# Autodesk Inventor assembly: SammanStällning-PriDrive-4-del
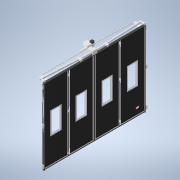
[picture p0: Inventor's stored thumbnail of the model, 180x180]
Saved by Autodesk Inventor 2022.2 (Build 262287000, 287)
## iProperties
Created: 2022-02
Part Number: SammanStällning-PriDrive-4-del
Document SubType Name: Assembly
Designer: cl
Author: cl
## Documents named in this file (23)
- G:\AutoCad\Carl Lund\3D-modeller systemlösningar\3D-modell-systemlösning-2022\SammanStällning-PriDrive-4-del.iam
- G:\AutoCad\Carl Lund\3D-modeller systemlösningar\3D-modell-systemlösning-2022\Parts\BladKomplett2022.iam
- G:\AutoCad\Carl Lund\3D-modeller systemlösningar\3D-modell-systemlösning-2022\Parts\MellanGångjärnH.ipt
- G:\AutoCad\Carl Lund\3D-modeller systemlösningar\3D-modell-systemlösning-2022\Parts\MellanGångjärnV.ipt
- G:\AutoCad\Carl Lund\3D-modeller systemlösningar\3D-modell-systemlösning-2022\Parts\Karmstyrning.ipt
- G:\AutoCad\Carl Lund\3D-modeller systemlösningar\3D-modell-systemlösning-2022\Parts\SidotätningUppe.ipt
- G:\AutoCad\Carl Lund\3D-modeller systemlösningar\3D-modell-systemlösning-2022\Parts\SidoTätning.ipt
- G:\AutoCad\Carl Lund\3D-modeller systemlösningar\3D-modell-systemlösning-2022\Parts\SläpList.ipt
- G:\AutoCad\Carl Lund\3D-modeller systemlösningar\3D-modell-systemlösning-2022\Parts\GummilistMellan.ipt
- G:\AutoCad\Carl Lund\3D-modeller systemlösningar\3D-modell-systemlösning-2022\Styrande.iam
- G:\AutoCad\Carl Lund\3D-modeller systemlösningar\3D-modell-systemlösning-2022\Parts\PriDrive\Karmgångjärn-PriDrive.ipt
- G:\AutoCad\Carl Lund\3D-modeller systemlösningar\3D-modell-systemlösning-2022\Parts\PriDrive\VinkeljärnStyrskena2.ipt
- G:\AutoCad\Carl Lund\3D-modeller systemlösningar\3D-modell-systemlösning-2022\Parts\PriDrive\VinkeljärnStyrskena.ipt
- G:\AutoCad\Carl Lund\3D-modeller systemlösningar\3D-modell-systemlösning-2022\Parts\StyrrulleH.ipt
- G:\AutoCad\Carl Lund\3D-modeller systemlösningar\3D-modell-systemlösning-2022\Parts\StyrrulleV.ipt
- G:\AutoCad\Carl Lund\3D-modeller systemlösningar\3D-modell-systemlösning-2022\Parts\MotorPlatta.ipt
- G:\AutoCad\Carl Lund\3D-modeller systemlösningar\3D-modell-systemlösning-2022\Parts\Länkarm-4Del.ipt
- G:\AutoCad\Carl Lund\3D-modeller systemlösningar\3D-modell-systemlösning-2022\Parts\Länkarm2-4Del.ipt
- G:\AutoCad\Carl Lund\3D-modeller systemlösningar\3D-modell-systemlösning-2022\Parts\MotorKåpa.ipt
- G:\AutoCad\Carl Lund\3D-modeller systemlösningar\3D-modell-systemlösning-2022\Parts\Motor.ipt
- G:\AutoCad\Carl Lund\3D-modeller systemlösningar\3D-modell-systemlösning-2022\Parts\Växellåda.ipt
- G:\AutoCad\Carl Lund\3D-modeller systemlösningar\3D-modell-systemlösning-2022\Parts\Styrskena-PD.ipt
- G:\AutoCad\Carl Lund\3D-modeller systemlösningar\3D-modell-systemlösning-2022\Parts\Logga.ipt
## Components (47 placed, 21 different names)
1. Logga:1 — Mate:196, Mate:197, Mate:198
2. BladKomplett2022:1 [sub-assembly] — Mate:1, Mate:2, Flush:1, Flush:2, Flush:3, Flush:8, Flush:28, Flush:29, Mate:28, Flush:30, Mate:42, Mate:39, Mate:43, Flush:99, Flush:100, Flush:101, Flush:102, Flush:103, Flush:104, Flush:112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
3. BladKomplett2022:2 [sub-assembly] — Flush:2, Flush:3, Flush:8, Flush:106, Mate:52, Flush:107, Flush:118, Flush:121, Mate:65, Flush:148, Flush:149, Mate:185, Flush:182, Flush:183, Flush:188, Mate:189
4. BladKomplett2022:3 [sub-assembly] — Flush:30, Flush:101, Flush:102, Mate:53, Flush:114, Flush:115, Flush:180
5. BladKomplett2022:4 [sub-assembly] — Flush:32, Flush:100, Flush:103, Mate:54, Flush:122, Flush:123, Flush:128, Mate:64, Flush:146, Flush:147, Flush:178
6. BladKomplett2022:5 [sub-assembly] — Flush:31, Flush:99, Flush:104, Flush:129, Mate:55, Flush:130, Mate:63, Flush:144, Flush:145, Mate:186, Flush:184, Flush:185, Flush:186, Flush:189
7. BladKomplett2022:6 [sub-assembly] — Mate:28, Flush:28, Flush:29, Flush:31, Flush:32, Mate:38, Flush:131, Flush:134, Flush:137, Mate:56, Flush:138, Flush:139, Mate:58, Mate:59, Mate:62, Flush:142, Flush:143, Flush:152, Mate:69, Mate:70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
8. Karmstyrning:2 — Mate:38, Mate:56, Flush:138, Flush:141
9. Karmstyrning:3 — Mate:39, Mate:43, Flush:140
10. Karmstyrning:4 — Mate:42, Mate:60, Mate:61, Flush:141
11. Karmstyrning:1 — Flush:139, Mate:58, Mate:59, Flush:140
12. MellanGångjärnV:3 — Flush:110, Flush:111, Flush:113
13. MellanGångjärnV:2 — Flush:108, Flush:109, Flush:110, Flush:111, Flush:112
14. MellanGångjärnV:1 — Flush:106, Mate:52, Flush:107, Flush:108, Flush:109
15. MellanGångjärnH:2 — Flush:116, Flush:117, Flush:118, Flush:119, Flush:120
16. MellanGångjärnH:3 — Flush:119, Flush:120, Flush:121
17. MellanGångjärnH:1 — Mate:53, Flush:114, Flush:115, Flush:116, Flush:117
18. MellanGångjärnV:6 — Flush:124, Flush:125, Flush:126, Flush:127, Flush:128
19. MellanGångjärnV:5 — Flush:126, Flush:127, Flush:129
20. MellanGångjärnV:4 — Mate:54, Flush:122, Flush:123, Flush:124, Flush:125
21. MellanGångjärnH:5 — Flush:132, Flush:133, Flush:134
22. MellanGångjärnH:6 — Flush:135, Flush:136, Flush:137
23. MellanGångjärnH:4 — Mate:55, Flush:130, Flush:131, Flush:132, Flush:133, Flush:135, Flush:136
24. GummilistMellan:2 — Mate:63, Flush:144, Flush:145
25. GummilistMellan:3 — Mate:64, Flush:146, Flush:147
26. GummilistMellan:4 — Mate:65, Flush:148, Flush:149
27. GummilistMellan:5 — Mate:66, Flush:150, Flush:151
28. SidotätningUppe:1 — Mate:67, Mate:68, Flush:152, Mate:71, Mate:74
29. SidoTätning:1 — Mate:69, Mate:70, Mate:71, Mate:76
30. SidoTätning:2 — Mate:72, Mate:73, Mate:74
31. SläpList:1 — Mate:75, Flush:153, Mate:76
32. GummilistMellan:1 — Mate:62, Flush:142, Flush:143
33. Karmgångjärn-PriDrive:1 — Mate:177, Flush:176, Mate:178, Flush:177, Flush:179, Mate:188, Tangent:3, Tangent:4
34. VinkeljärnStyrskena2:1 — Flush:179, Flush:180, Mate:181, Mate:183, Flush:187
35. VinkeljärnStyrskena2:2 — Flush:177, Flush:178, Mate:180, Flush:181, Mate:184
36. VinkeljärnStyrskena:1 — Mate:182, Flush:181, Flush:186
37. VinkeljärnStyrskena:2 — Mate:187, Flush:187, Flush:188
38. StyrrulleH:1 — Mate:185, Flush:182, Flush:183, Tangent:2
39. StyrrulleV:1 — Mate:186, Flush:184, Flush:185, Tangent:1
40. Styrskena-PD:2 — Flush:174, Mate:181, Mate:183, Tangent:2, Mate:187
41. Styrskena-PD:1 — Flush:174, Mate:179, Mate:180, Mate:182, Mate:184, Tangent:1
42. Länkarm-4Del:1 — Flush:190, Mate:190, Tangent:3, Flush:191
43. Länkarm2-4Del:1 — Mate:191, Flush:191, Tangent:4
44. MotorKåpa:1 — Mate:195, Flush:195, Flush:196
45. Motor:1 — Mate:193, Flush:194, Mate:194, Mate:195, Flush:195, Flush:196
46. Växellåda:1 — Mate:192, Flush:192, Flush:193, Flush:194, Mate:194
47. MotorPlatta:1 — Mate:188, Flush:189, Mate:189, Flush:190, Mate:190, Mate:191, Mate:192, Flush:192, Flush:193, Mate:193
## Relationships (142: Flush 85, Mate 53, Tangent 4)
- Mate:1: BladKomplett2022:1
- Mate:2: BladKomplett2022:1
- Flush:1: BladKomplett2022:1
- Flush:2: BladKomplett2022:1 ↔ BladKomplett2022:2
- Flush:3: BladKomplett2022:1 ↔ BladKomplett2022:2
- Flush:8: BladKomplett2022:1 ↔ BladKomplett2022:2
- Mate:28: BladKomplett2022:1 ↔ BladKomplett2022:6
- Flush:28: BladKomplett2022:1 ↔ BladKomplett2022:6
- Flush:29: BladKomplett2022:1 ↔ BladKomplett2022:6
- Flush:30: BladKomplett2022:1 ↔ BladKomplett2022:3
- Flush:31: BladKomplett2022:5 ↔ BladKomplett2022:6
- Flush:32: BladKomplett2022:4 ↔ BladKomplett2022:6
- Mate:38: BladKomplett2022:6 ↔ Karmstyrning:2
- Mate:39: BladKomplett2022:1 ↔ Karmstyrning:3
- Mate:42: BladKomplett2022:1 ↔ Karmstyrning:4
- Mate:43: BladKomplett2022:1 ↔ Karmstyrning:3
- Flush:99: BladKomplett2022:1 ↔ BladKomplett2022:5
- Flush:100: BladKomplett2022:1 ↔ BladKomplett2022:4
- Flush:101: BladKomplett2022:1 ↔ BladKomplett2022:3
- Flush:102: BladKomplett2022:1 ↔ BladKomplett2022:3
- Flush:103: BladKomplett2022:1 ↔ BladKomplett2022:4
- Flush:104: BladKomplett2022:1 ↔ BladKomplett2022:5
- Flush:106: BladKomplett2022:2 ↔ MellanGångjärnV:1
- Mate:52: BladKomplett2022:2 ↔ MellanGångjärnV:1
- Flush:107: BladKomplett2022:2 ↔ MellanGångjärnV:1
- Flush:108: MellanGångjärnV:2 ↔ MellanGångjärnV:1
- Flush:109: MellanGångjärnV:2 ↔ MellanGångjärnV:1
- Flush:110: MellanGångjärnV:3 ↔ MellanGångjärnV:2
- Flush:111: MellanGångjärnV:3 ↔ MellanGångjärnV:2
- Flush:112: BladKomplett2022:1 ↔ MellanGångjärnV:2
- Flush:113: BladKomplett2022:1 ↔ MellanGångjärnV:3
- Mate:53: BladKomplett2022:3 ↔ MellanGångjärnH:1
- Flush:114: BladKomplett2022:3 ↔ MellanGångjärnH:1
- Flush:115: BladKomplett2022:3 ↔ MellanGångjärnH:1
- Flush:116: MellanGångjärnH:2 ↔ MellanGångjärnH:1
- Flush:117: MellanGångjärnH:2 ↔ MellanGångjärnH:1
- Flush:118: BladKomplett2022:2 ↔ MellanGångjärnH:2
- Flush:119: MellanGångjärnH:2 ↔ MellanGångjärnH:3
- Flush:120: MellanGångjärnH:2 ↔ MellanGångjärnH:3
- Flush:121: BladKomplett2022:2 ↔ MellanGångjärnH:3
- Mate:54: BladKomplett2022:4 ↔ MellanGångjärnV:4
- Flush:122: BladKomplett2022:4 ↔ MellanGångjärnV:4
- Flush:123: BladKomplett2022:4 ↔ MellanGångjärnV:4
- Flush:124: MellanGångjärnV:6 ↔ MellanGångjärnV:4
- Flush:125: MellanGångjärnV:6 ↔ MellanGångjärnV:4
- Flush:126: MellanGångjärnV:6 ↔ MellanGångjärnV:5
- Flush:127: MellanGångjärnV:6 ↔ MellanGångjärnV:5
- Flush:128: BladKomplett2022:4 ↔ MellanGångjärnV:6
- Flush:129: BladKomplett2022:5 ↔ MellanGångjärnV:5
- Mate:55: BladKomplett2022:5 ↔ MellanGångjärnH:4
- Flush:130: BladKomplett2022:5 ↔ MellanGångjärnH:4
- Flush:131: BladKomplett2022:6 ↔ MellanGångjärnH:4
- Flush:132: MellanGångjärnH:5 ↔ MellanGångjärnH:4
- Flush:133: MellanGångjärnH:5 ↔ MellanGångjärnH:4
- Flush:134: BladKomplett2022:6 ↔ MellanGångjärnH:5
- Flush:135: MellanGångjärnH:6 ↔ MellanGångjärnH:4
- Flush:136: MellanGångjärnH:6 ↔ MellanGångjärnH:4
- Flush:137: BladKomplett2022:6 ↔ MellanGångjärnH:6
- Mate:56: BladKomplett2022:6 ↔ Karmstyrning:2
- Flush:138: BladKomplett2022:6 ↔ Karmstyrning:2
- Flush:139: BladKomplett2022:6 ↔ Karmstyrning:1
- Mate:58: BladKomplett2022:6 ↔ Karmstyrning:1
- Mate:59: BladKomplett2022:6 ↔ Karmstyrning:1
- Flush:140: Karmstyrning:3 ↔ Karmstyrning:1
- Mate:60: BladKomplett2022:1 ↔ Karmstyrning:4
- Mate:61: BladKomplett2022:1 ↔ Karmstyrning:4
- Flush:141: Karmstyrning:2 ↔ Karmstyrning:4
- Mate:62: BladKomplett2022:6 ↔ GummilistMellan:1
- Flush:142: BladKomplett2022:6 ↔ GummilistMellan:1
- Flush:143: BladKomplett2022:6 ↔ GummilistMellan:1
- Mate:63: BladKomplett2022:5 ↔ GummilistMellan:2
- Flush:144: BladKomplett2022:5 ↔ GummilistMellan:2
- Flush:145: BladKomplett2022:5 ↔ GummilistMellan:2
- Mate:64: BladKomplett2022:4 ↔ GummilistMellan:3
- Flush:146: BladKomplett2022:4 ↔ GummilistMellan:3
- Flush:147: BladKomplett2022:4 ↔ GummilistMellan:3
- Mate:65: BladKomplett2022:2 ↔ GummilistMellan:4
- Flush:148: BladKomplett2022:2 ↔ GummilistMellan:4
- Flush:149: BladKomplett2022:2 ↔ GummilistMellan:4
- Mate:66: BladKomplett2022:1 ↔ GummilistMellan:5
- Flush:150: BladKomplett2022:1 ↔ GummilistMellan:5
- Flush:151: BladKomplett2022:1 ↔ GummilistMellan:5
- Mate:67: BladKomplett2022:1 ↔ SidotätningUppe:1
- Mate:68: BladKomplett2022:1 ↔ SidotätningUppe:1
- Flush:152: BladKomplett2022:6 ↔ SidotätningUppe:1
- Mate:69: BladKomplett2022:6 ↔ SidoTätning:1
- Mate:70: BladKomplett2022:6 ↔ SidoTätning:1
- Mate:71: SidotätningUppe:1 ↔ SidoTätning:1
- Mate:72: BladKomplett2022:1 ↔ SidoTätning:2
- Mate:73: BladKomplett2022:1 ↔ SidoTätning:2
- Mate:74: SidotätningUppe:1 ↔ SidoTätning:2
- Mate:75: BladKomplett2022:1 ↔ SläpList:1
- Flush:153: BladKomplett2022:1 ↔ SläpList:1
- Mate:76: SidoTätning:1 ↔ SläpList:1
- Flush:174: Styrskena-PD:2 ↔ Styrskena-PD:1
- Mate:177: BladKomplett2022:1 ↔ Karmgångjärn-PriDrive:1
- Flush:176: BladKomplett2022:1 ↔ Karmgångjärn-PriDrive:1
- Mate:178: BladKomplett2022:1 ↔ Karmgångjärn-PriDrive:1
- Flush:177: Karmgångjärn-PriDrive:1 ↔ VinkeljärnStyrskena2:2
- Flush:178: BladKomplett2022:4 ↔ VinkeljärnStyrskena2:2
- Mate:179: BladKomplett2022:6 ↔ Styrskena-PD:1
- Mate:180: VinkeljärnStyrskena2:2 ↔ Styrskena-PD:1
- Flush:179: Karmgångjärn-PriDrive:1 ↔ VinkeljärnStyrskena2:1
- Flush:180: BladKomplett2022:3 ↔ VinkeljärnStyrskena2:1
- Mate:181: VinkeljärnStyrskena2:1 ↔ Styrskena-PD:2
- Mate:182: VinkeljärnStyrskena:1 ↔ Styrskena-PD:1
- Flush:181: VinkeljärnStyrskena2:2 ↔ VinkeljärnStyrskena:1
- Mate:183: VinkeljärnStyrskena2:1 ↔ Styrskena-PD:2
- Mate:184: VinkeljärnStyrskena2:2 ↔ Styrskena-PD:1
- Mate:185: BladKomplett2022:2 ↔ StyrrulleH:1
- Flush:182: BladKomplett2022:2 ↔ StyrrulleH:1
- Flush:183: BladKomplett2022:2 ↔ StyrrulleH:1
- Mate:186: BladKomplett2022:5 ↔ StyrrulleV:1
- Flush:184: BladKomplett2022:5 ↔ StyrrulleV:1
- Flush:185: BladKomplett2022:5 ↔ StyrrulleV:1
- Tangent:1: StyrrulleV:1 ↔ Styrskena-PD:1
- Tangent:2: StyrrulleH:1 ↔ Styrskena-PD:2
- Flush:186: BladKomplett2022:5 ↔ VinkeljärnStyrskena:1
- Mate:187: VinkeljärnStyrskena:2 ↔ Styrskena-PD:2
- Flush:187: VinkeljärnStyrskena2:1 ↔ VinkeljärnStyrskena:2
- Flush:188: BladKomplett2022:2 ↔ VinkeljärnStyrskena:2
- Mate:188: Karmgångjärn-PriDrive:1 ↔ MotorPlatta:1
- Flush:189: BladKomplett2022:5 ↔ MotorPlatta:1
- Mate:189: BladKomplett2022:2 ↔ MotorPlatta:1
- Flush:190: Länkarm-4Del:1 ↔ MotorPlatta:1
- Mate:190: Länkarm-4Del:1 ↔ MotorPlatta:1
- Tangent:3: Karmgångjärn-PriDrive:1 ↔ Länkarm-4Del:1
- Mate:191: Länkarm2-4Del:1 ↔ MotorPlatta:1
- Flush:191: Länkarm-4Del:1 ↔ Länkarm2-4Del:1
- Tangent:4: Karmgångjärn-PriDrive:1 ↔ Länkarm2-4Del:1
- Mate:192: Växellåda:1 ↔ MotorPlatta:1
- Flush:192: Växellåda:1 ↔ MotorPlatta:1
- Flush:193: Växellåda:1 ↔ MotorPlatta:1
- Mate:193: Motor:1 ↔ MotorPlatta:1
- Flush:194: Motor:1 ↔ Växellåda:1
- Mate:194: Motor:1 ↔ Växellåda:1
- Mate:195: MotorKåpa:1 ↔ Motor:1
- Flush:195: MotorKåpa:1 ↔ Motor:1
- Flush:196: MotorKåpa:1 ↔ Motor:1
- Mate:196: Logga:1 ↔ BladKomplett2022:6
- Mate:197: Logga:1 ↔ BladKomplett2022:6
- Mate:198: Logga:1 ↔ BladKomplett2022:6
## Named parameters: Blad2 = 1012.5 mm, Blad3 = 0, Blad4 = 0, Blad5 = 1012.5 mm, MGJ12Djup = 0, MGJ12Bredd = 0, MGJ56Djup = 0, MGJ56Bredd = 0, MGJ23Djup = 48 mm, MGJ45Djup = 48 mm, GarageRegel5 = 0, GarageRegel6 = 0, BladBredd = 987.5 mm, Fönsterhöjd = 862 mm, Blad2_1 = 1012.5 mm, Blad3_1 = 0, Blad4_1 = 0, Blad5_1 = 1012.5 mm, Blad6 = 2025 mm, MGJ12Djup_1 = 0, MGJ12Bredd_1 = 0, MGJ2Djup = 0, MGJ2Bredd = 5012.5 mm, MGJ56Djup_1 = 0, MGJ56Bredd_1 = 0, MGJ23Djup_1 = 48 mm, MGJ45Djup_1 = 48 mm, GarageRegel5_1 = 0, GarageRegel6_1 = 0, Styrrulle2Djup = 0, FönsterhöjdStyrning = 862 mm, FönsterKarm = 54 mm, AndraGlasraden = 0, BrösthöjdStyrning2 = 0.0001 mm, InfälldGångDörr = 0, Infälldstyr = 1012.5 mm, EnDelGångDörr = 0, VinkelJärnStyrSkena = 1456.25 mm
